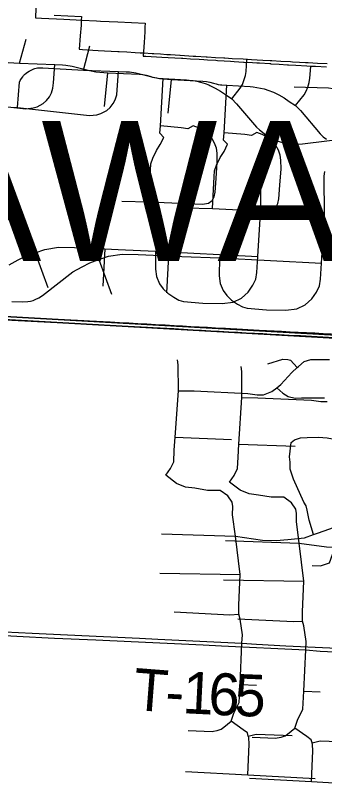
# Model space of a CAD drawing. Extents: x -38.2 to 41.9, y -4 to 24.9.
# Drawn here: x 6.57 to 6.989, y 15.71 to 16.76 of the extents above; entities that cross this region are included whole.
import ezdxf

# ---------------------------------------------------------------- set-up
doc = ezdxf.new("R2010")
doc.units = 0
for name, color, linetype in [('Default', 7, 'Continuous'), ('GM_X_City_Street', 7, 'Continuous'), ('GM_X_County_Road', 7, 'Continuous'), ('GM_X_County_Text', 7, 'Continuous'), ('GM_X_Interchange_Ramps', 7, 'Continuous'), ('GM_X_Interstate_Location', 7, 'Continuous'), ('GM_X_State_Location', 7, 'Continuous'), ('GM_X_Township_Road', 7, 'Continuous'), ('GM_X_Township_Road_Text', 7, 'Continuous'), ('SH_Cut_Line', 7, 'Continuous')]:
    doc.layers.add(name, color=color, linetype=linetype)

msp = doc.modelspace()

# ---------------------------------------------------------------- linework, layer by layer
at = {"layer": 'Default'}
msp.add_lwpolyline([(6.6222, 16.7605), (6.659, 16.7587), (6.6588, 16.7533), (6.6585, 16.747), (6.6575, 16.7325), (6.6562, 16.7142), (6.6603, 16.714), (6.6674, 16.7136), (6.6816, 16.7128), (6.6903, 16.7123), (6.7083, 16.7113), (6.7102, 16.7112), (6.7209, 16.7106), (6.7322, 16.7099), (6.7387, 16.7096), (6.7436, 16.7093), (6.755, 16.7086), (6.7574, 16.7084), (6.7664, 16.7079), (6.775, 16.7073), (6.7801, 16.707), (6.7927, 16.7062), (6.7933, 16.7062), (6.8047, 16.7055), (6.8108, 16.7051), (6.8142, 16.7049), (6.8282, 16.704), (6.8291, 16.704), (6.8298, 16.7039), (6.8411, 16.7032), (6.8525, 16.7025), (6.8535, 16.7025), (6.8638, 16.7019), (6.8785, 16.7011), (6.8844, 16.7007), (6.8901, 16.7005), (6.9055, 16.6996), (6.9154, 16.6991), (6.9176, 16.6989), (6.9296, 16.6983), (6.9428, 16.6975), (6.9454, 16.6974), (6.9549, 16.6969), (6.9632, 16.6964), (6.967, 16.6962), (6.9793, 16.6955), (6.9926, 16.6948)], dxfattribs=at)
at = {"layer": 'GM_X_City_Street'}
for p, q in [((6.7863, 16.1885), (6.8627, 16.1856)), ((6.7679, 16.0575), (6.868, 16.0542)), ((6.7656, 16.0043), (6.8745, 16.0025)), ((6.8745, 15.8533), (6.8967, 15.8525))]:
    msp.add_line(p, q, dxfattribs=at)
for points in [[(6.7736, 16.1369), (6.78, 16.1459), (6.7843, 16.1551), (6.7851, 16.1709), (6.7863, 16.1885), (6.7906, 16.2515), (6.7902, 16.2866), (6.7896, 16.2935)], [(6.7906, 16.2515), (6.8121, 16.2513), (6.8848, 16.2478), (6.8977, 16.2461), (6.9063, 16.2461), (6.9175, 16.2506), (6.9241, 16.2556), (6.9298, 16.2599), (6.9447, 16.276), (6.9521, 16.2828), (6.9537, 16.2843), (6.9614, 16.291), (6.9704, 16.2938), (6.9956, 16.294)], [(6.9119, 16.2881), (6.9323, 16.2943), (6.9391, 16.294), (6.9428, 16.293), (6.9521, 16.2828)], [(6.9241, 16.2556), (6.9324, 16.248), (6.9399, 16.2438), (6.949, 16.2413), (6.9576, 16.2417), (6.9889, 16.2419)], [(6.9436, 16.1815), (6.9484, 16.185), (6.9563, 16.1877), (6.9654, 16.1882), (6.9807, 16.1886), (6.9924, 16.1875), (6.9999, 16.1862), (7.0069, 16.1829), (7.0099, 16.1796), (7.0082, 16.1728), (7.0066, 16.1655), (7.0022, 16.1545), (7.0002, 16.147), (7.0017, 16.1411), (7.0053, 16.1363), (7.0113, 16.1321), (7.0185, 16.1306), (7.033, 16.1318), (7.0562, 16.1309), (7.0868, 16.127), (7.1097, 16.1242), (7.1254, 16.1258)], [(6.9739, 16.0565), (6.9684, 16.0763), (6.9656, 16.0897), (6.964, 16.0953), (6.961, 16.1004), (6.947, 16.1316), (6.9425, 16.145), (6.9423, 16.1548), (6.9413, 16.1618), (6.9436, 16.1815)], [(6.8576, 16.109), (6.8474, 16.1164), (6.8303, 16.1164), (6.8131, 16.1193), (6.8001, 16.121), (6.788, 16.1259), (6.7736, 16.1369)], [(6.8728, 15.9486), (6.8727, 15.9611), (6.8745, 16.0025), (6.868, 16.0542), (6.8643, 16.0834), (6.8647, 16.0944), (6.8636, 16.1004), (6.8576, 16.109)], [(6.868, 16.0542), (6.905, 16.0491), (6.9235, 16.0485), (6.9391, 16.0499), (6.962, 16.0523), (6.9739, 16.0565), (6.9793, 16.0583), (6.9961, 16.0644), (7.0094, 16.0694), (7.025, 16.0689), (7.0792, 16.068), (7.0978, 16.0705), (7.1092, 16.067), (7.1308, 16.0619)], [(6.9722, 16.0148), (6.9836, 16.0143), (6.9956, 16.0185), (6.9998, 16.0297), (7.025, 16.0689)], [(6.785, 15.9517), (6.8607, 15.9479), (6.8728, 15.9486)], [(6.877, 15.9094), (6.8775, 15.9209), (6.8747, 15.9419), (6.8728, 15.9486)], [(6.8624, 15.8036), (6.8659, 15.8144), (6.8733, 15.8292), (6.8745, 15.8533), (6.877, 15.9094)], [(6.8041, 15.7912), (6.8364, 15.7898), (6.8382, 15.7903), (6.8435, 15.791), (6.8489, 15.793), (6.8525, 15.7954), (6.8624, 15.8036)], [(6.8849, 15.731), (6.8866, 15.7724), (6.8862, 15.7815), (6.8856, 15.7835), (6.8843, 15.7877), (6.8784, 15.7921), (6.8624, 15.8036)], [(6.8856, 15.7835), (6.8964, 15.7861), (6.9451, 15.7843)], [(6.8005, 15.7356), (6.8849, 15.731), (6.9765, 15.7259)]]:
    msp.add_lwpolyline(points, dxfattribs=at)
at = {"layer": 'GM_X_County_Road'}
for points in [[(6.5978, 16.7831), (6.5965, 16.7568), (6.6048, 16.7564), (6.6352, 16.7549), (6.6599, 16.7537), (6.6793, 16.7527), (6.6848, 16.7524), (6.7086, 16.7513), (6.7455, 16.7495), (6.7453, 16.7441), (6.745, 16.7378), (6.744, 16.7233), (6.7427, 16.7051), (6.7467, 16.7048), (6.7539, 16.7044), (6.7681, 16.7036), (6.7768, 16.7031), (6.7948, 16.7021), (6.7967, 16.702), (6.8073, 16.7014), (6.8187, 16.7007), (6.8252, 16.7004), (6.8301, 16.7001), (6.8415, 16.6994), (6.8438, 16.6992), (6.8529, 16.6987), (6.8615, 16.6981), (6.8665, 16.6978), (6.8792, 16.697), (6.8798, 16.697), (6.8912, 16.6963), (6.8973, 16.6959), (6.9007, 16.6957), (6.9147, 16.6948), (6.9155, 16.6948), (6.9162, 16.6947), (6.9276, 16.6941), (6.939, 16.6933), (6.94, 16.6933), (6.9503, 16.6927), (6.965, 16.6919), (6.9709, 16.6915), (6.9766, 16.6913), (6.9919, 16.6904)], [(7.0173, 16.3225), (6.9867, 16.3241), (6.9565, 16.3257), (6.9477, 16.3261), (6.941, 16.3265), (6.9276, 16.3272), (6.9166, 16.3278), (6.9053, 16.3285), (6.894, 16.3291), (6.8827, 16.3297), (6.8714, 16.3304), (6.859, 16.331), (6.8461, 16.3318), (6.8344, 16.3324), (6.822, 16.3331), (6.8097, 16.3338), (6.7974, 16.3345), (6.7847, 16.3352), (6.7564, 16.3367), (6.7487, 16.3372), (6.6349, 16.343), (6.5203, 16.3489)], [(6.9987, 16.328), (6.9874, 16.3287), (6.976, 16.3293), (6.9534, 16.3305), (6.9422, 16.3311), (6.9308, 16.3317), (6.9003, 16.3333), (6.87, 16.3349), (6.8612, 16.3353), (6.8545, 16.3357), (6.8411, 16.3364), (6.8301, 16.337), (6.8188, 16.3377), (6.8075, 16.3383), (6.7962, 16.3389), (6.7849, 16.3396), (6.7726, 16.3402), (6.7596, 16.341), (6.7479, 16.3416), (6.7355, 16.3423), (6.7232, 16.343), (6.7109, 16.3437), (6.6982, 16.3444), (6.6699, 16.3459), (6.6622, 16.3464), (6.5484, 16.3522)]]:
    msp.add_lwpolyline(points, dxfattribs=at)
at = {"layer": 'GM_X_Interchange_Ramps'}
for points in [[(5.6874, 16.3954), (5.9853, 16.3764), (6.413, 16.3602), (6.4263, 16.3595), (7.1336, 16.3198), (7.3442, 16.3107), (7.5793, 16.2961), (7.6901, 16.2894), (7.9696, 16.2752), (8.9, 16.2272), (8.9, 17.7063), (8.9, 17.9093), (8.9, 20.9), (5.1243, 20.9)], [(5.7739, 16.3862), (6.0718, 16.3672), (6.4995, 16.351), (6.5128, 16.3503), (7.2201, 16.3106), (7.4307, 16.3015), (7.6658, 16.2869), (7.7766, 16.2803), (8.0561, 16.266), (8.9, 16.2225), (8.9, 20.9), (5.2114, 20.9)], [(7.1336, 16.3198), (6.4263, 16.3595), (6.413, 16.3602), (6.4072, 16.1101), (6.4038, 15.9323), (6.3986, 15.8377), (6.3824, 15.5439), (6.3792, 15.4548), (6.3746, 15.3485), (6.3744, 15.3416), (6.3648, 15.1855), (6.3534, 14.8912), (6.3402, 14.6363), (6.3239, 14.3451), (6.322, 14.2869), (6.322, 14.2806), (6.3207, 14.2654), (6.3196, 14.2542), (6.3164, 14.1849), (6.3126, 14.1), (8.8984, 14.1)], [(7.2201, 16.3106), (6.5128, 16.3503), (6.4995, 16.351), (6.4937, 16.1009), (6.4903, 15.9231), (6.4851, 15.8285), (6.4689, 15.5348), (6.4657, 15.4456), (6.4611, 15.3393), (6.4608, 15.3324), (6.4513, 15.1763), (6.4399, 14.882), (6.4267, 14.6271), (6.4104, 14.3359), (6.4085, 14.2777), (6.4084, 14.2714), (6.4072, 14.2562), (6.4061, 14.245), (6.4028, 14.1757), (6.3995, 14.1), (8.9, 14.1)]]:
    msp.add_lwpolyline(points, dxfattribs=at)
at = {"layer": 'GM_X_Interstate_Location'}
for p, q in [((6.8728, 16.1793), (6.9492, 16.1764)), ((6.8544, 16.0484), (6.9545, 16.045)), ((6.852, 15.9951), (6.961, 15.9933)), ((6.9609, 15.8442), (6.9832, 15.8433))]:
    msp.add_line(p, q, dxfattribs=at)
for points in [[(6.8601, 16.1277), (6.8665, 16.1367), (6.8708, 16.1459), (6.8716, 16.1617), (6.8728, 16.1793), (6.877, 16.2423), (6.8767, 16.2774), (6.876, 16.2843)], [(6.877, 16.2423), (6.8985, 16.2421), (6.9713, 16.2387), (6.9842, 16.2369), (6.9928, 16.237)], [(6.9441, 16.0998), (6.9338, 16.1072), (6.9168, 16.1073), (6.8996, 16.1101), (6.8866, 16.1118), (6.8745, 16.1167), (6.8601, 16.1277)], [(6.9593, 15.9394), (6.9592, 15.9519), (6.961, 15.9933), (6.9545, 16.045), (6.9508, 16.0742), (6.9512, 16.0852), (6.95, 16.0912), (6.9441, 16.0998)], [(6.9545, 16.045), (6.9915, 16.0399), (7.01, 16.0393), (7.0256, 16.0407), (7.0485, 16.0431), (7.0604, 16.0473), (7.0657, 16.0491), (7.0826, 16.0552), (7.0959, 16.0602), (7.1115, 16.0597), (7.1657, 16.0588), (7.1843, 16.0613), (7.1957, 16.0578), (7.2173, 16.0528)], [(6.8715, 15.9426), (6.9472, 15.9387), (6.9593, 15.9394)], [(6.9635, 15.9002), (6.964, 15.9117), (6.9611, 15.9327), (6.9593, 15.9394)], [(6.9489, 15.7944), (6.9524, 15.8052), (6.9598, 15.8201), (6.9609, 15.8442), (6.9635, 15.9002)], [(6.8906, 15.782), (6.9229, 15.7806), (6.9247, 15.7811), (6.93, 15.7818), (6.9354, 15.7838), (6.939, 15.7862), (6.9489, 15.7944)], [(6.9713, 15.7218), (6.9731, 15.7633), (6.9727, 15.7723), (6.9721, 15.7743), (6.9708, 15.7785), (6.9649, 15.7829), (6.9489, 15.7944)], [(6.9721, 15.7743), (6.9829, 15.7769), (7.0316, 15.7751)], [(6.887, 15.7265), (6.9713, 15.7218), (7.063, 15.7167)]]:
    msp.add_lwpolyline(points, dxfattribs=at)
at = {"layer": 'GM_X_State_Location'}
for p, q in [((6.6617, 16.6861), (6.6705, 16.7189)), ((6.7767, 16.6276), (6.7812, 16.6731)), ((6.6827, 16.4293), (6.7001, 16.3822)), ((6.7773, 16.4344), (6.7745, 16.3842))]:
    msp.add_line(p, q, dxfattribs=at)
for points in [[(6.5721, 16.6353), (6.5748, 16.6699), (6.5759, 16.6719), (6.5766, 16.6732), (6.5776, 16.6748), (6.5793, 16.6771), (6.5806, 16.6786), (6.582, 16.68), (6.5841, 16.6819), (6.5859, 16.6833), (6.5881, 16.6847), (6.5916, 16.6865), (6.5945, 16.6876), (6.5959, 16.6881), (6.5975, 16.6885), (6.5995, 16.6889), (6.6026, 16.6892), (6.6068, 16.6893), (6.6617, 16.6861), (6.7092, 16.6842), (6.7199, 16.6838), (6.7244, 16.6836), (6.7327, 16.6823), (6.7564, 16.6763), (6.7652, 16.6747), (6.7812, 16.6731)], [(6.9496, 16.6379), (6.9612, 16.6524), (6.964, 16.6575), (6.9662, 16.6628), (6.9681, 16.6694), (6.9691, 16.675), (6.9703, 16.691)], [(6.5265, 16.6375), (6.5721, 16.6353), (6.67, 16.6245), (6.6799, 16.6255), (6.6856, 16.6272), (6.6934, 16.6315), (6.698, 16.6355), (6.7023, 16.6408), (6.7047, 16.6458), (6.7069, 16.6524), (6.7076, 16.6594), (6.7092, 16.6842)], [(6.7812, 16.6731), (6.824, 16.6712), (6.8287, 16.6708), (6.8335, 16.6698), (6.8382, 16.6685), (6.842, 16.6674), (6.8448, 16.6667), (6.8477, 16.6662), (6.8497, 16.666), (6.8564, 16.6655), (6.888, 16.6636), (6.892, 16.6633), (6.8971, 16.6626), (6.9021, 16.6617), (6.9071, 16.6605), (6.9136, 16.6585), (6.9184, 16.6567), (6.92, 16.656), (6.9272, 16.6524), (6.9344, 16.6483), (6.9412, 16.6436), (6.9496, 16.6379), (6.9562, 16.6312), (6.983, 16.5995), (6.9872, 16.5958), (6.9915, 16.5925)], [(6.8372, 16.4984), (6.8393, 16.5412), (6.8398, 16.5497), (6.8423, 16.5574), (6.8474, 16.5677), (6.8526, 16.5758), (6.8573, 16.5857), (6.8518, 16.5913), (6.8527, 16.6011), (6.8564, 16.6655)], [(6.8002, 16.4994), (6.8372, 16.4984), (6.9098, 16.495), (6.9178, 16.4965), (6.9229, 16.5), (6.9255, 16.5051), (6.927, 16.5116), (6.9285, 16.53), (6.93, 16.5522), (6.9297, 16.5641), (6.9288, 16.5709), (6.9264, 16.5777), (6.9229, 16.5839), (6.9181, 16.5899), (6.911, 16.5952), (6.9045, 16.5988), (6.8971, 16.6014), (6.8899, 16.5974), (6.881, 16.5988), (6.8527, 16.6011)], [(6.8463, 16.4315), (6.846, 16.4071), (6.8475, 16.3969), (6.8515, 16.3874), (6.8563, 16.3804), (6.8628, 16.3744), (6.871, 16.3689), (6.8777, 16.3652), (6.884, 16.3632), (6.9102, 16.3612), (6.9364, 16.3607), (6.9516, 16.3625), (6.9628, 16.368), (6.9718, 16.3759), (6.9783, 16.3852), (6.982, 16.3937), (6.9835, 16.4027), (6.9851, 16.4242), (6.9892, 16.4895), (6.9885, 16.5421), (6.9896, 16.5488)], [(6.5647, 16.3726), (6.5794, 16.372), (6.5865, 16.3724), (6.59, 16.3731), (6.5934, 16.374), (6.5961, 16.375), (6.6012, 16.3776), (6.6061, 16.3805), (6.6474, 16.4128), (6.6599, 16.4196), (6.6703, 16.4249), (6.6827, 16.4293), (6.696, 16.4338), (6.7143, 16.4368), (6.7362, 16.4362), (6.7773, 16.4344), (6.7953, 16.4335), (6.8463, 16.4315), (6.9851, 16.4242)], [(6.4966, 15.9228), (6.5713, 15.919), (6.6225, 15.9163), (6.6786, 15.9137), (6.7266, 15.9116), (6.8243, 15.907)], [(6.8243, 15.907), (6.8492, 15.9058), (6.9635, 15.9002), (6.9832, 15.8987), (7.0229, 15.8968)]]:
    msp.add_lwpolyline(points, dxfattribs=at)
at = {"layer": 'GM_X_Township_Road'}
for p, q in [((6.5752, 16.6953), (6.584, 16.7281)), ((6.6903, 16.6368), (6.6948, 16.6823)), ((6.9027, 16.4987), (6.9652, 16.4972)), ((6.5962, 16.4385), (6.6136, 16.3913)), ((6.6908, 16.4436), (6.688, 16.3934))]:
    msp.add_line(p, q, dxfattribs=at)
for points in [[(6.8631, 16.647), (6.8747, 16.6616), (6.8775, 16.6667), (6.8797, 16.672), (6.8816, 16.6786), (6.8826, 16.6842), (6.8838, 16.7002)], [(6.4401, 16.6467), (6.4856, 16.6445), (6.5835, 16.6337), (6.5934, 16.6347), (6.5991, 16.6363), (6.6069, 16.6407), (6.6115, 16.6447), (6.6158, 16.65), (6.6183, 16.655), (6.6204, 16.6616), (6.6211, 16.6686), (6.6228, 16.6934)], [(6.5203, 16.6985), (6.5752, 16.6953), (6.6228, 16.6934), (6.6334, 16.693), (6.6379, 16.6928), (6.6463, 16.6915), (6.6699, 16.6855), (6.6788, 16.6839), (6.6948, 16.6823)], [(6.6948, 16.6823), (6.7376, 16.6804), (6.7423, 16.6799), (6.7471, 16.679), (6.7518, 16.6777), (6.7555, 16.6766), (6.7584, 16.6759), (6.7613, 16.6754), (6.7632, 16.6752), (6.7699, 16.6747), (6.8015, 16.6728), (6.8055, 16.6724), (6.8106, 16.6718), (6.8156, 16.6709), (6.8206, 16.6697), (6.8271, 16.6677), (6.8319, 16.6659), (6.8335, 16.6652), (6.8407, 16.6616), (6.8479, 16.6575), (6.8547, 16.6528), (6.8631, 16.647), (6.8697, 16.6404), (6.8965, 16.6087), (6.9007, 16.605), (6.905, 16.6017), (6.9102, 16.5976), (6.9134, 16.5951), (6.9178, 16.5925), (6.9286, 16.5887), (6.9357, 16.5869), (6.9429, 16.5859), (6.9512, 16.5855), (6.959, 16.586), (7.0287, 16.5949)], [(6.7507, 16.5076), (6.7529, 16.5503), (6.7533, 16.5589), (6.7558, 16.5666), (6.761, 16.5769), (6.7661, 16.585), (6.7708, 16.5949), (6.7653, 16.6005), (6.7662, 16.6103), (6.7699, 16.6747)], [(7.0287, 16.5949), (7.025, 16.6327), (7.024, 16.6374), (7.0221, 16.6423), (7.0195, 16.647), (7.0162, 16.6511), (7.0122, 16.6548), (7.0078, 16.6577), (7.0041, 16.6594), (7.0001, 16.6607), (6.9946, 16.6617), (6.9477, 16.6629)], [(6.7137, 16.5086), (6.7507, 16.5076), (6.8234, 16.5042), (6.8314, 16.5057), (6.8364, 16.5092), (6.8391, 16.5143), (6.8405, 16.5208), (6.842, 16.5392), (6.8435, 16.5614), (6.8432, 16.5733), (6.8423, 16.5801), (6.8399, 16.5869), (6.8364, 16.5931), (6.8316, 16.5991), (6.8245, 16.6044), (6.818, 16.608), (6.8106, 16.6106), (6.8034, 16.6066), (6.7946, 16.608), (6.7662, 16.6103)], [(6.7598, 16.4406), (6.7596, 16.4163), (6.7611, 16.4061), (6.765, 16.3966), (6.7698, 16.3896), (6.7763, 16.3836), (6.7845, 16.3781), (6.7913, 16.3744), (6.7975, 16.3724), (6.8237, 16.3704), (6.8499, 16.3699), (6.8651, 16.3716), (6.8763, 16.3771), (6.8853, 16.3851), (6.8918, 16.3944), (6.8956, 16.4029), (6.8971, 16.4118), (6.8986, 16.4334), (6.9027, 16.4987), (6.902, 16.5513), (6.9031, 16.558), (6.9055, 16.5672), (6.9088, 16.5761), (6.9107, 16.5803), (6.9178, 16.5925)], [(6.5609, 16.422), (6.5734, 16.4287), (6.5839, 16.4341), (6.5962, 16.4385), (6.6095, 16.443), (6.6278, 16.446), (6.6497, 16.4454), (6.6908, 16.4436), (6.7089, 16.4427), (6.7598, 16.4406), (6.8986, 16.4334)], [(6.4102, 15.932), (6.4848, 15.9282), (6.536, 15.9255), (6.5921, 15.9229), (6.6402, 15.9208), (6.7378, 15.9162)], [(6.7378, 15.9162), (6.7627, 15.915), (6.877, 15.9094), (6.8967, 15.9079), (6.9365, 15.906)], [(6.9365, 15.906), (6.9861, 15.9036), (7.0157, 15.9024), (7.0797, 15.8992), (7.0955, 15.8982)]]:
    msp.add_lwpolyline(points, dxfattribs=at)
at = {"layer": 'SH_Cut_Line'}
for points in [[(5.6874, 16.3954), (5.9853, 16.3764), (6.413, 16.3602), (6.4263, 16.3595), (7.1336, 16.3198), (7.3442, 16.3107), (7.5793, 16.2961), (7.6901, 16.2894), (7.9696, 16.2752), (8.9, 16.2272), (8.9, 17.7063), (8.9, 17.9093), (8.9, 20.9), (2.1103, 20.9)], [(2.1, 14.1), (8.9, 14.1), (8.9, 16.2272), (7.9696, 16.2752), (7.6901, 16.2894), (7.5793, 16.2961), (7.3442, 16.3107), (7.1336, 16.3198), (6.4263, 16.3595), (6.413, 16.3602), (5.9853, 16.3764), (5.6874, 16.3954)]]:
    msp.add_lwpolyline(points, dxfattribs=at)

# ---------------------------------------------------------------- texts
at = {"layer": 'GM_X_County_Text'}
msp.add_text('DELAWARE COUNTY', height=0.189394, dxfattribs=at).set_placement((5.943, 16.4275))
at = {"layer": 'GM_X_Township_Road_Text'}
for s, rotation, p in [('T', 355.5513, (6.728, 15.8192)), ('1', 357.1261, (6.7954, 15.8146)), ('6', 357.1753, (6.8304, 15.8128)), ('5', 357.7379, (6.866, 15.8111)), ('-', 356.9188, (6.7719, 15.8158))]:
    msp.add_text(s, height=0.0568, rotation=rotation, dxfattribs=at).set_placement(p)

doc.saveas('drawing.dxf')
